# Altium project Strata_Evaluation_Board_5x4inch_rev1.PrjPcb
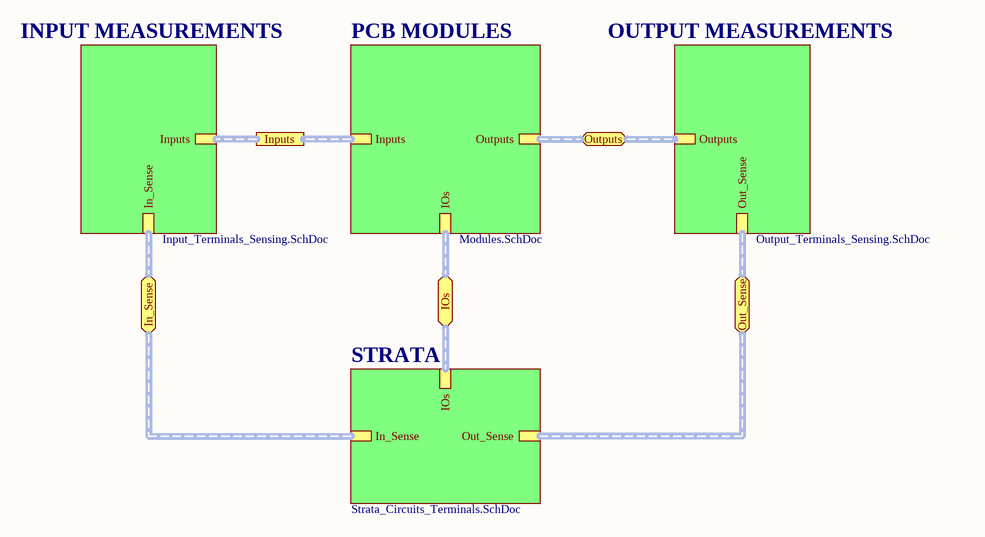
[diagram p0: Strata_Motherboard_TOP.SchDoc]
Project_Author: Miroslav Hukel; Project_CompanyName: ON Semiconductor Slovakia; Project_DateCreated: 01-12-2019; Project_DateModified: DD-MM-YYYY; Project_DocumentNumber: BA0362OA; Project_Revision: O; Project_Title: Strata PCB Module Evaluation Board
5 sheets, 99 parts. Net scope: hierarchical (ports join the sheet entries above them; power ports are global).
Board file: Strata_Evaluation_Board_5x4inch_rev1.PcbDoc
Sheets:
  Strata_Motherboard_TOP.SchDoc
    PCB MODULES = Modules.SchDoc
    OUTPUT MEASUREMENTS = Output_Terminals_Sensing.SchDoc
    STRATA = Strata_Circuits_Terminals.SchDoc
    INPUT MEASUREMENTS = Input_Terminals_Sensing.SchDoc

## Sheet Strata_Motherboard_TOP.SchDoc: =Project_Title
size A4; Author: F. Valero / T. Krecek; CompanyName: ON Semiconductor Slovakia; DocumentNumber: BA0362OA; Revision: 1

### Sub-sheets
INPUT MEASUREMENTS = Input_Terminals_Sensing.SchDoc: Inputs (harness Inputs), In_Sense (harness In_Sense)
OUTPUT MEASUREMENTS = Output_Terminals_Sensing.SchDoc: Outputs (harness Outputs), Out_Sense (harness Out_Sense)
PCB MODULES = Modules.SchDoc: Outputs (harness Outputs), IOs (harness IOs), Inputs (harness Inputs)
STRATA = Strata_Circuits_Terminals.SchDoc: IOs (harness IOs), In_Sense (harness In_Sense), Out_Sense (harness Out_Sense)

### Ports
In_Sense (bidir), Inputs, IOs (bidir), Out_Sense (bidir), Outputs (bidir)

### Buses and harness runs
harness port In_Sense = sheet INPUT MEASUREMENTS/In_Sense = sheet STRATA/In_Sense
harness port Inputs = sheet INPUT MEASUREMENTS/Inputs = sheet PCB MODULES/Inputs
harness port IOs = sheet PCB MODULES/IOs = sheet STRATA/IOs
harness port Out_Sense = sheet OUTPUT MEASUREMENTS/Out_Sense = sheet STRATA/Out_Sense
harness port Outputs = sheet OUTPUT MEASUREMENTS/Outputs = sheet PCB MODULES/Outputs

## Sheet Modules.SchDoc: =Project_ProductNumber + ' ' + Project_Title1 + ' ' + Project_Title2
size A3; Author: F. Valero / T. Krecek; CompanyName: ON Semiconductor Slovakia; DocumentNumber: BA0362OA; Revision: 1; SheetNumber: 1; SheetTotal: 2
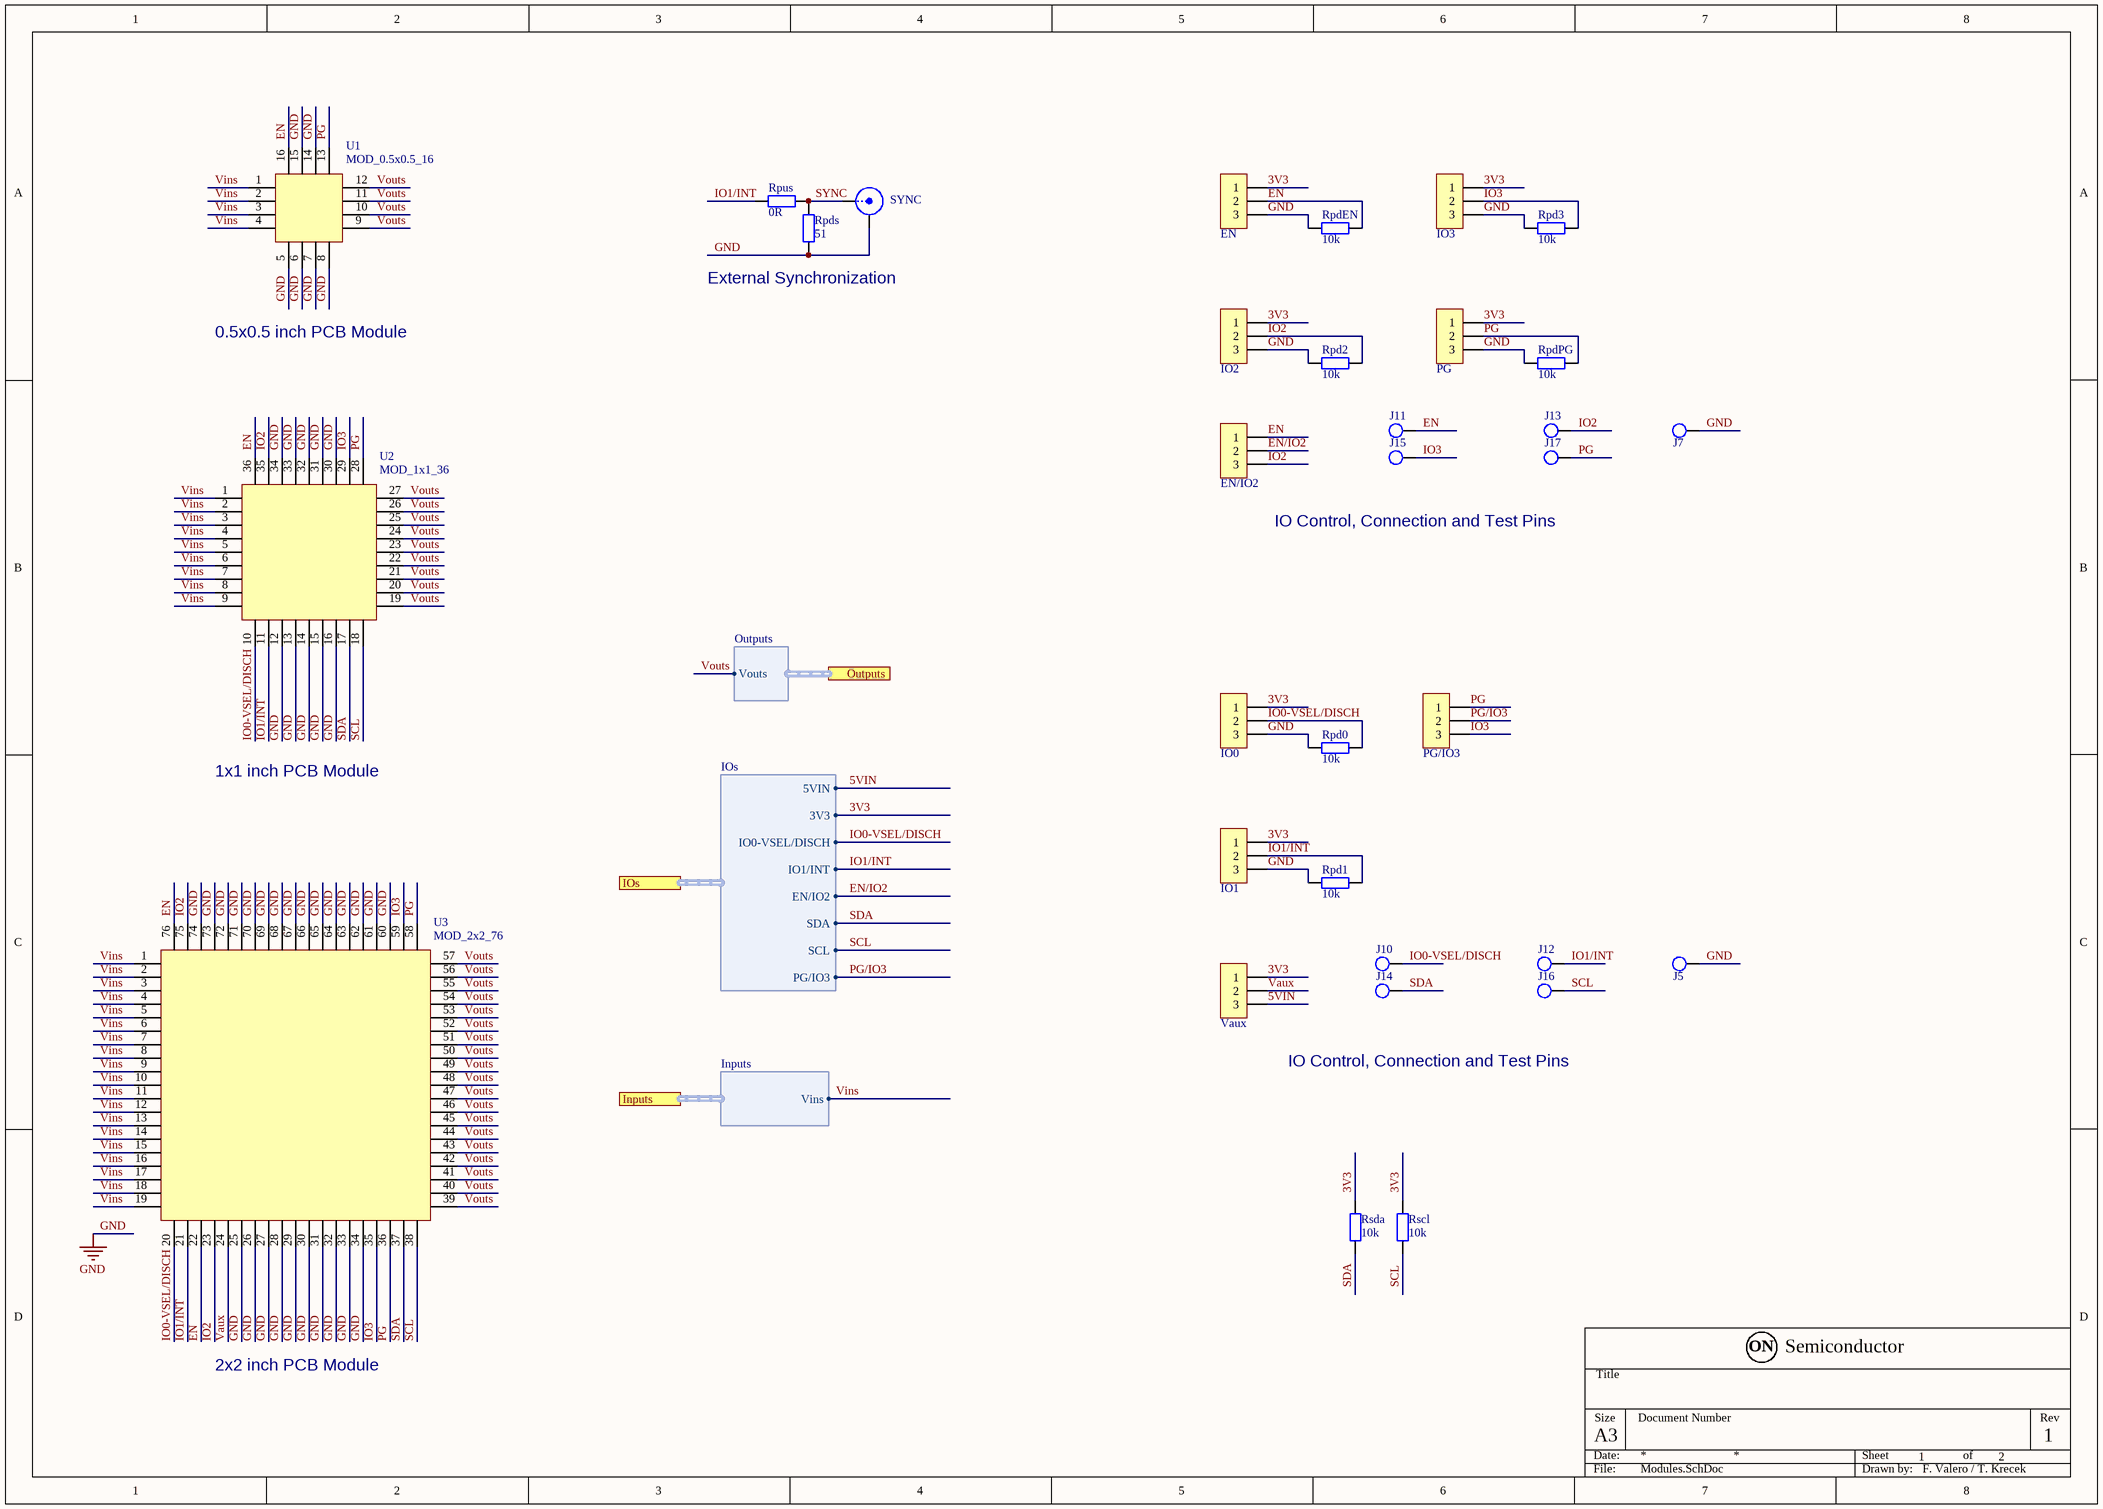
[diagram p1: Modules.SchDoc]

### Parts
EN  22-28-4360  [Header_3]  (value not drawn)
EN/IO2  22-28-4360  [Header_3]  (value not drawn)
IO0  22-28-4360  [Header_3]  (value not drawn)
IO1  22-28-4360  [Header_3]  (value not drawn)
IO2  22-28-4360  [Header_3]  (value not drawn)
IO3  22-28-4360  [Header_3]  (value not drawn)
J5  160-1026-02-01-00  [Terminal Turret]  (value not drawn)
J7  160-1026-02-01-00  [Terminal Turret]  (value not drawn)
J10  5010  [TestPoint_1.6mm]  (value not drawn)
J11  5010  [TestPoint_1.6mm]  (value not drawn)
J12  5010  [TestPoint_1.6mm]  (value not drawn)
J13  5010  [TestPoint_1.6mm]  (value not drawn)
J14  5010  [TestPoint_1.6mm]  (value not drawn)
J15  5010  [TestPoint_1.6mm]  (value not drawn)
J16  5010  [TestPoint_1.6mm]  (value not drawn)
J17  5010  [TestPoint_1.6mm]  (value not drawn)
PG  22-28-4360  [Header_3]  (value not drawn)
PG/IO3  22-28-4360  [Header_3]  (value not drawn)
Rpd0  value 10k  [0603_RES]  (hidden comment: RC0603FR-0710KL)
Rpd1  value 10k  [0603_RES]  (hidden comment: RC0603FR-0710KL)
Rpd2  value 10k  [0603_RES]  (hidden comment: RC0603FR-0710KL)
Rpd3  value 10k  [0603_RES]  (hidden comment: RC0603FR-0710KL)
RpdEN  value 10k  [0603_RES]  (hidden comment: RC0603FR-0710KL)
RpdPG  value 10k  [0603_RES]  (hidden comment: RC0603FR-0710KL)
Rpds  value 51  [0603_RES]  (hidden comment: RC0603FR-0751RL)
Rpus  value 0R  [0603_RES]  (hidden comment: Short)
Rscl  value 10k  [0603_RES]  (hidden comment: RC0603FR-0710KL)
Rsda  value 10k  [0603_RES]  (hidden comment: RC0603FR-0710KL)
SYNC  SMB_STR_TH_50OHM  [SMB_STR_TH]  (value not drawn)
U1  MOD_0.5x0.5_16  [MOD_0.5x0.5_16]
U2  MOD_1x1_36  [MOD_1x1_36]
U3  MOD_2x2_76  [MOD_2x2_76]
Vaux  22-28-4360  [Header_3]  (value not drawn)

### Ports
Inputs (harness Inputs), IOs (harness IOs), Outputs (harness Outputs)

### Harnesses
Outputs: Vouts
Inputs: Vins
IOs: EN/IO2, IO0-VSEL/DISCH, IO1/INT, SDA, PG/IO3, SCL, 3V3, 5VIN

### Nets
GND: EN.3 IO0.3 IO1.3 IO2.3 IO3.3 J5.1 J7.1 PG.3 Rpd0.2 Rpd1.2 Rpd2.2 Rpd3.2 RpdEN.2 RpdPG.2 Rpds.2 SYNC.2 U1.5 U1.6 U1.7 U1.8 U1.14 U1.15 U2.12 U2.13 U2.14 U2.15 U2.16 U2.30 U2.31 U2.32 U2.33 U2.34 U3.25 U3.26 U3.27 U3.28 U3.29 U3.30 U3.31 U3.32 U3.33 U3.34 U3.60 U3.61 U3.62 U3.63 U3.64 U3.65 U3.66 U3.67 U3.68 U3.69 U3.70 U3.71 U3.72 U3.73 U3.74
3V3: EN.1 IO0.1 IO1.1 IO2.1 IO3.1 PG.1 Rscl.1 Rsda.1 Vaux.1 ; port IOs.3V3
5VIN: Vaux.3 ; port IOs.5VIN
EN: EN.2 EN/IO2.1 J11.1 RpdEN.1 U1.16 U2.36 U3.22 U3.76
EN/IO2: EN/IO2.2 ; port IOs.EN/IO2
IO0-VSEL/DISCH: IO0.2 J10.1 Rpd0.1 U2.10 U3.20 ; port IOs.IO0-VSEL/DISCH
IO1/INT: IO1.2 J12.1 Rpd1.1 Rpus.1 U2.11 U3.21 ; port IOs.IO1/INT
IO2: EN/IO2.3 IO2.2 J13.1 Rpd2.1 U2.35 U3.23 U3.75
IO3: IO3.2 J15.1 PG/IO3.3 Rpd3.1 U2.29 U3.35 U3.59
PG: J17.1 PG.2 PG/IO3.1 RpdPG.1 U1.13 U2.28 U3.36 U3.58
PG/IO3: PG/IO3.2 ; port IOs.PG/IO3
SCL: J16.1 Rscl.2 U2.18 U3.38 ; port IOs.SCL
SDA: J14.1 Rsda.2 U2.17 U3.37 ; port IOs.SDA
SYNC: Rpds.1 Rpus.2 SYNC.1
Vaux: U3.24 Vaux.2
Vins: U1.1 U1.2 U1.3 U1.4 U2.1 U2.2 U2.3 U2.4 U2.5 U2.6 U2.7 U2.8 U2.9 U3.1 U3.2 U3.3 U3.4 U3.5 U3.6 U3.7 U3.8 U3.9 U3.10 U3.11 U3.12 U3.13 U3.14 U3.15 U3.16 U3.17 U3.18 U3.19 ; port Inputs.Vins
Vouts: U1.9 U1.10 U1.11 U1.12 U2.19 U2.20 U2.21 U2.22 U2.23 U2.24 U2.25 U2.26 U2.27 U3.39 U3.40 U3.41 U3.42 U3.43 U3.44 U3.45 U3.46 U3.47 U3.48 U3.49 U3.50 U3.51 U3.52 U3.53 U3.54 U3.55 U3.56 U3.57 ; port Outputs.Vouts

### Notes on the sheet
- (near Rpds) External Synchronization
- 0.5x0.5 inch PCB Module
- IO Control, Connection and Test Pins
- 1x1 inch PCB Module
- 2x2 inch PCB Module

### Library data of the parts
EN EN/IO2 IO0-IO3 PG PG/IO3 Vaux = Header3_EB_IO: Board-To-Board Connector; Header; 36;  22-28-4360; Manufacturer: Würth electronics; MPN: 61300311121; Signature Author: Zemanovic; Value/Rating: 3 POS; Value: 3 POS; Substitution Allowed: Yes
J5 J7 = TestPoint_2.37mm: TestPoint; 2.37mm; TH; CAMBION  160-1026-02-01-00  TERMINAL; Signature Author: Nagy; Substitution Allowed: Yes
J10-J17 = TestPoint_1.6mm: TestPoint; 1.6mm; TH; Keystone 5010; Signature Author: Nagy; Substitution Allowed: Yes
Rpd0-Rpd3 RpdEN RpdPG Rscl Rsda = 10k_0603_1%: 10k; 1/10W; 1%; 0603; Yageo; Signature Author: Hukel; Value/Rating: 10k/1/10W; Substitution Allowed: Yes
Rpds = 51_0603_1%: 51; 1/10W; 1%; 0603; Yageo; Signature Author: Hukel; Value/Rating: 51/1/10W; Substitution Allowed: Yes
Rpus = 0R_0603: RES SMD 0 OHM JUMPER 0603; Yageo; MPN: RC2512JK-070RL; Signature Author: Hukel; Rating: 1W; Value/Rating: 0R/1W; Substitution Allowed: Yes
SYNC = SMB_STR_TH_50OHM: SMB JACK STR; 50 OHM; TH; 1-1337482-0; Manufacturer: TE Connectivity; Signature Author: Zemanovic; Substitution Allowed: Yes
U1 = MOD_0.5x0.5_16: PCB Footprint for 0.5 x 0.5 inch PCB Module; Substitution Allowed: No
U2 = MOD_1x1_36: PCB Footprint for 1 x 1 inch PCB Module; Substitution Allowed: No
U3 = MOD_2x2_76: PCB Footprint for 2 x 2 inch PCB Module; Substitution Allowed: No

## Sheet Output_Terminals_Sensing.SchDoc: =Project_Title
size A4; Author: F. Valero / T. Krecek; CompanyName: ON Semiconductor Slovakia; DocumentNumber: BA0362OA; Revision: 1
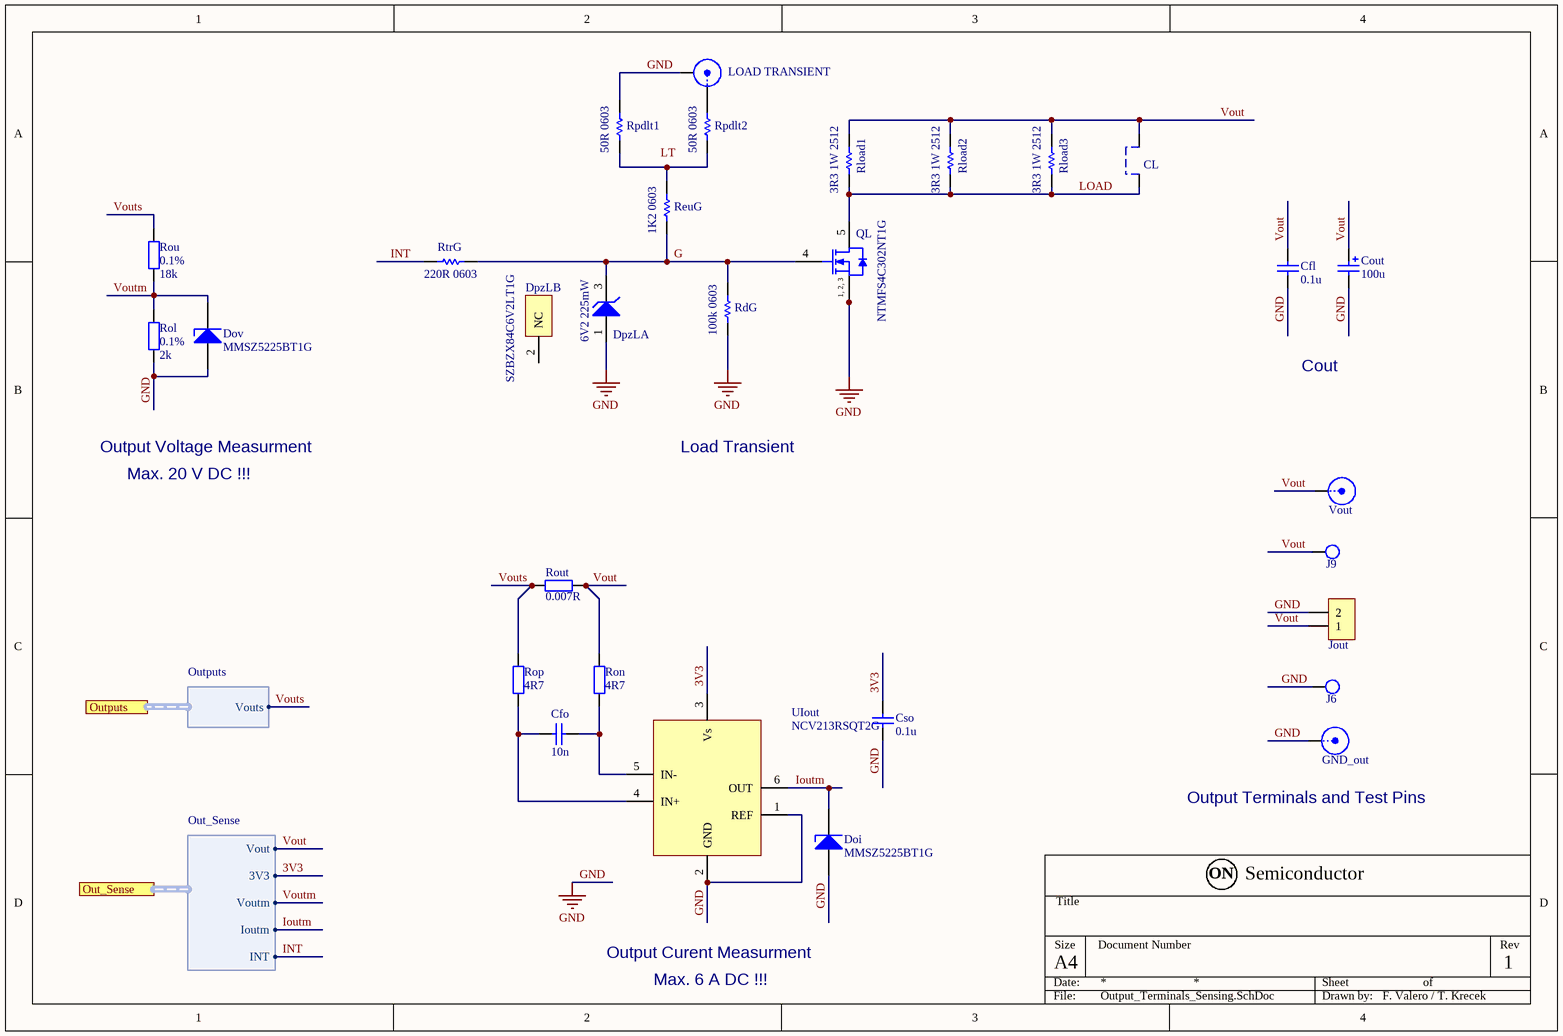
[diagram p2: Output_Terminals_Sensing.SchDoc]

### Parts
Cfl  value 0.1u  [0603_CAP_MAX]  (hidden comment: GCJ188R71H104KA12D)
Cfo  value 10n  [0603_CAP]  (hidden comment: GCJ188R71H103KA01D)
CL  Current Loop for 2.5 sqmm Cu wire  [Current_Loop_2.5sqmm]  (value not drawn)
Cout  value 100u  [Elyt_Radial_10X12.5]  (hidden comment: EEUFR1J101B)
Cso  value 0.1u  [0603_CAP]  (hidden comment: GCJ188R71H104KA12D)
Doi  MMSZ5225BT1G  [SOD-123]
Dov  MMSZ5225BT1G  [SOD-123]
DpzL  6V2 225mW  [ONSC-SOT-23-3-318-08_V]  (parts A,B of 2)
GND_out  571-0100-01  [PCB Jack 4mm - black]  (value not drawn)
J6  160-1026-02-01-00  [Terminal Turret]  (value not drawn)
J9  5010  [TestPoint_1.6mm]  (value not drawn)
Jout  OSTTC022162  [ED120/2DS]  (value not drawn)
LOAD_TRANSIENT  SMB_STR_TH_50OHM  [SMB_STR_TH]  (value not drawn)
QL  NTMFS4C302NT1G  [ONSC-DFN-5-488AA_V]
RdG  100k 0603  [RESC1608X55X25ML10T15]
ReuG  1K2 0603  [RESC1608X55X25LL10T15]
Rload1  3R3 1W 2512  [RESC2512(6432)_N]
Rload2  3R3 1W 2512  [RESC2512(6432)_N]
Rload3  3R3 1W 2512  [RESC2512(6432)_N]
Rol  value 2k  Tolerance: 0.1%  [0603_RES]  (hidden comment: RT0603BRD072KL)
Ron  value 4R7  [0603_RES]  (hidden comment: RC0603FR-074R7L)
Rop  value 4R7  [0603_RES]  (hidden comment: RC0603FR-074R7L)
Rou  value 18k  Tolerance: 0.1%  [0603_RES]  (hidden comment: RT0603BRD0718KL)
Rout  value 0.007R  [2512_RES]  (hidden comment: PE2512FKE7W0R007L)
Rpdlt1  50R 0603  [RESC1609X50X30NL10T20]
Rpdlt2  50R 0603  [RESC1609X50X30NL10T20]
RtrG  220R 0603  [RESC1608X55X25ML10T15]
UIout  value NCV213RSQT2G  [SC-88/SC70-6/SOT-363]  (hidden comment: NCS213R)
Vout  571-0500-01  [PCB Jack 4mm - red]  (value not drawn)

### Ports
Out_Sense (harness Out_Sense), Outputs (harness Outputs)

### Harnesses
Outputs: Vouts
Out_Sense: Voutm, Ioutm, 3V3, Vout, INT

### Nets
GND: Cfl.2 Cout.2 Cso.2 Doi.2(A) Dov.2(A) DpzL.1(A) GND_out.1 J6.1 Jout.2 LOAD_TRANSIENT.2 QL.1(S) QL.2(S) QL.3(S) RdG.2 Rol.2 Rpdlt1.2 UIout.1(REF) UIout.2(GND)
3V3: Cso.1 UIout.3(Vs) ; port Out_Sense.3V3
G: DpzL.3(K) QL.4(G) RdG.1 ReuG.1 RtrG.2
INT: RtrG.1 ; port Out_Sense.INT
Ioutm: Doi.1(K) UIout.6(OUT) ; port Out_Sense.Ioutm
LOAD: CL.1 QL.5(D) Rload1.1 Rload2.1 Rload3.1
Vout: Cfl.1 CL.2 Cout.1 J9.1 Jout.1 Rload1.2 Rload2.2 Rload3.2 Ron.1 Rout.2 Vout.1 ; port Out_Sense.Vout
Voutm: Dov.1(K) Rol.1 Rou.2 ; port Out_Sense.Voutm
Vouts: Rop.1 Rou.1 Rout.1 ; port Outputs.Vouts
NetCfo_1: Cfo.1 Ron.2 UIout.5(IN-)
NetCfo_2: Cfo.2 Rop.2 UIout.4(IN+)
NetLOAD_TRANSIENT_1: LOAD_TRANSIENT.1 Rpdlt2.2
NetReuG_2: ReuG.2 Rpdlt1.1 Rpdlt2.1

Not connected (* = marked no-connect by the designer): DpzL 2(NC)

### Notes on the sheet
- Cout
- Output Voltage Measurment
- Max. 20 V DC !!!
- Load Transient
- (near GND_out) Output Terminals and Test Pins
- Output Curent Measurment
- Max. 6 A DC !!!
- Labels drawn without touching a wire or pin: LT

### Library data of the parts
Cfl Cso = GCJ188R71H104KA12D: 0.1uF; 50V; X7R; 10%; 0603; GRM188R70J474KA01D; Murata; Signature Author: Hukel; Substitution Allowed: Yes; Value/Rating: 0.1u/50V
Cfo = GCJ188R71H103KA01D: 10nF; 50V; X7R; 10%; 0603; GCJ188R71H103KA01D; Murata; Signature Author: Hukel; Substitution Allowed: Yes; Value/Rating: 10n/50V
CL = Current_Loop_2.5sqmm: Current Loop Wire for Osciloscope Current Probe; Signature Author: Hukel; Rating: 1W; Tolerance: Wire Loop; Value/Rating: 0.005/1W; Substitution Allowed: Yes; Value: 0.005
Cout = 100uF_Rad_63V_ELYT: 100uF; 63 V; 20%; EEUFR1J101B; Panasonic; MPN: EEU-FR1J101B; Signature Author: Zemanovic; Rating: 63V; Value/Rating: 100u/63V; Substitution Allowed: Yes
Doi Dov = MMSZ5225BT1G: MMSZ52xxxT1G; 3.0V/0.5W; SOD-123; ON Semiconductor; Signature Author: Nagy; Tolerance: 5%; Substitution Allowed: Yes
DpzL = CMP-1060-00917-1: Zener Voltage Regulator, 225 mW, 3-Pin SOT-23, Pb-Free, Tape and Reel; Manufacturer: On Semiconductor; MPN: SZBZX84C6V2LT1G
GND_out = Banana_Socket_10A_Black: 10A; 4mm; TH; Black; 571-0100-01 ; DELTRON; Signature Author: Nagy; Substitution Allowed: Yes
J6 = TestPoint_2.37mm: as J5 on sheet Modules
J9 = TestPoint_1.6mm: as J10 on sheet Modules
Jout = Screw_Terminal_Large: Large Screw Terminal,  TERM BLK 2P SIDE ENT 5.08MM PCB; Manufacturer: Samtec; Signature Author: Zemanovic; Value/Rating: TSW-102-07-G-S; Value: TSW-102-07-G-S; Substitution Allowed: Yes
LOAD_TRANSIENT = SMB_STR_TH_50OHM: as SYNC on sheet Modules
QL = CMP-1058-00242-1: Single N−Channel Logic Level Power MOSFET, 30 V, 230 A, 1.15 mΩ; Manufacturer: On Semiconductor; Channel Polarity: N Channel; Packing: Tape and Reel; VGS Max (V): 20; VGS(th) Max (V): 2.2; V(BR)DSS Min (V): 30
RdG = CMP-2100-03662-1: Chip Resistor, 100 KOhm, +/- 1%, 0.1 W, -55 to 155 degC, 0603 (1608 Metric), RoHS, Tape and Reel; Manufacturer: Yageo; MPN: RC0603FR-07100KL; Power Rating: 100mW; Voltage Rating: 50V; Temperature Coefficient: 100ppm/degreesC
ReuG = CMP-2000-06952-1: Chip Resistor, 1.2 KOhm, +/- 5%, 0.1 W, -55 to 155 degC, 0603 (1608 Metric), RoHS, Tape and Reel; Manufacturer: Yageo; MPN: RC0603JR-071K2L; Temperature Coefficient: 100PPM/C; Resistance: 1.2kOhms; Power Rating: 100mW; Voltage Rating: 50V
Rload1-Rload3 = CMP-1018-00014-1: 3R3 1W 5% 2512 (6432 Metric)  SMD; Manufacturer: Vishay Dale; MPN: CRCW25123R30JNEG; Value: 3.30 Ohm; Case-EIA: 2512; Case-Metric: 6432
Rol = 1k_0603_0.01%: RES SMD 2K OHM 0.1% 1 / 10W 0603; Manufacturer: Yageo; Signature Author: Valero; Rating: 1/10W; Value/Rating: 2k/1/10W; Substitution Allowed: Yes
Ron Rop = 4.7_0603_1%_1: 4.7; 1/10W; 1%; 0603; Yageo; Signature Author: Hukel; Value/Rating: 4R7/1/10W; Substitution Allowed: Yes
Rou = 5.6k_0603_0.01%: 18 kOhms ± 0.1% 0.1W, 1 / 10W chip resistance 0603 (1608 metric) thin film; Manufacturer: Yageo; Signature Author: Valero; Rating: 1/10W; Value/Rating: 18k/1/10W; Substitution Allowed: Yes
Rout = 0.010R_2512_0.5%: RES SMD 0.007 OHM 2W 2512; Yageo; Signature Author: Hukel; Tolerance: 1%; Value/Rating: 0.007R/2W; Substitution Allowed: Yes
Rpdlt1 Rpdlt2 = CMP-2000-03436-1: Chip Resistor, 50 Ohm, +/- 1%, 0.1 W, -55 to 155 degC, 0603 (1608 Metric), RoHS, Tape and Reel; MPN: CRCW060350R0FKEA; Manufacturer: Vishay Dale
RtrG = CMP-1659-00018-2: General Purpose Chip Resistors, 220 Ohm, +/- 1%, -55 to 155 degC, 0603 (1608 Metric), RoHS, Tape and Reel; MPN: RC0603FR-07220RL
UIout = NCS213R: Current-Shunt Monitors, Voltage Output, Bidirectional Zero-Drift, Low- or High-Side Current Sensing; SO-8; ON Semiconductor; Signature Author: Hukel; Substitution Allowed: No
Vout = Banana_Socket_10A_Red: 10A; 4mm; TH; Red; 571-0500-01 ; DELTRON; Signature Author: Nagy; Substitution Allowed: Yes

## Sheet Strata_Circuits_Terminals.SchDoc: =Project_Title
size A4; Author: F. Valero / T. Krecek; CompanyName: ON Semiconductor Slovakia; DocumentNumber: BA0362OA; Revision: 1
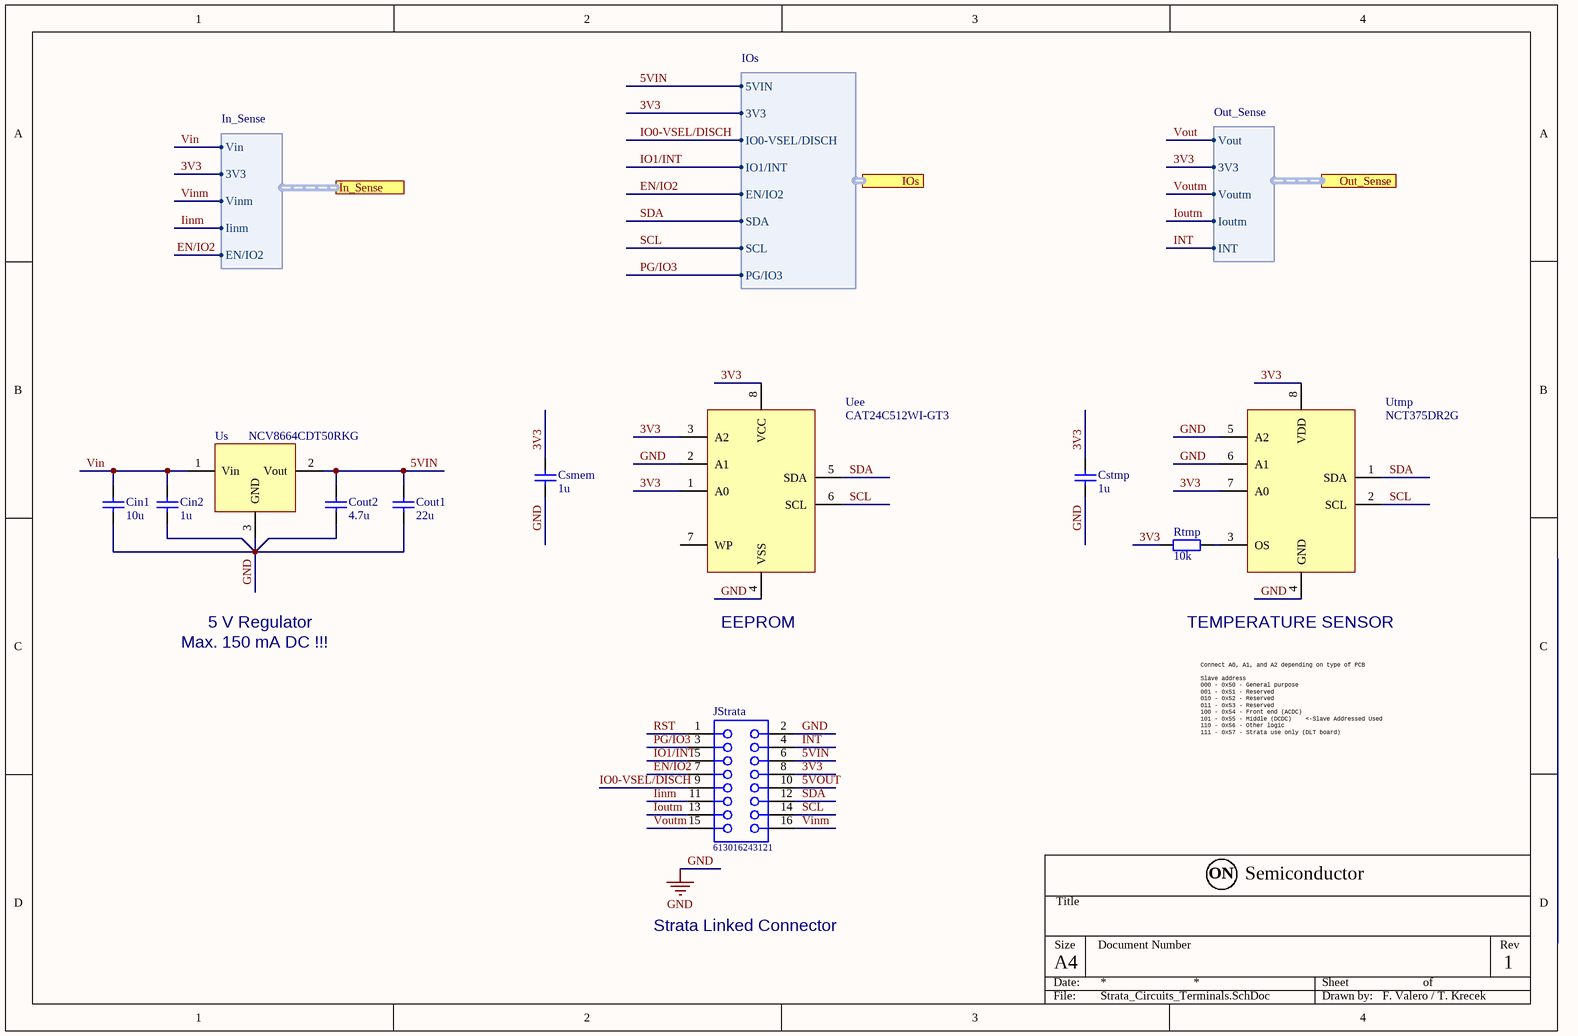
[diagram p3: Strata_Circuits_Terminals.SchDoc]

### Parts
Cin1  value 10u  [1206_CAP]  (hidden comment: GRT31CR71E106KE13)
Cin2  value 1u  [0805_CAP_MAX]  (hidden comment: GCM21BR71H105KA03L)
Cout1  value 22u  [1206_CAP_MAX]  (hidden comment: GCM31CR71A226KE02L)
Cout2  value 4.7u  [0805_CAP_MAX]  (hidden comment: GCM21BR71C475KA73L)
Csmem  value 1u  [0805_CAP_MAX]  (hidden comment: GCM21BR71H105KA03L)
Cstmp  value 1u  [0805_CAP_MAX]  (hidden comment: GCM21BR71H105KA03L)
JStrata  613016243121  [613016243121_Strata]
Rtmp  value 10k  [0603_RES]  (hidden comment: RC0603FR-0710KL)
Uee  value CAT24C512WI-GT3  [SOIC-8]  (hidden comment: CAT24C512)
Us  value NCV8664CDT50RKG  [DPAK-3_L]  (hidden comment: NCV8664CDT50)
Utmp  value NCT375DR2G  [SOIC-8]  (hidden comment: NCT375)

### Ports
In_Sense (harness In_Sense), IOs (harness IOs), Out_Sense (harness Out_Sense)

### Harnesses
In_Sense: Vinm, Iinm, 3V3, Vin, EN/IO2
Out_Sense: Voutm, Ioutm, 3V3, Vout, INT
IOs: EN/IO2, IO0-VSEL/DISCH, IO1/INT, SDA, PG/IO3, SCL, 3V3, 5VIN

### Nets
GND: Cin1.2 Cin2.2 Cout1.2 Cout2.2 Csmem.2 Cstmp.2 JStrata.2 Uee.2(A1) Uee.4(VSS) Us.3(GND) Utmp.4(GND) Utmp.5(A2) Utmp.6(A1)
3V3: Csmem.1 Cstmp.1 JStrata.8 Rtmp.1 Uee.1(A0) Uee.3(A2) Uee.8(VCC) Utmp.7(A0) Utmp.8(VDD) ; port In_Sense.3V3, port Out_Sense.3V3, port IOs.3V3
5VIN: Cout1.1 Cout2.1 JStrata.6 Us.2(Vout) ; port IOs.5VIN
5VOUT: JStrata.10
EN/IO2: JStrata.7 ; port In_Sense.EN/IO2, port IOs.EN/IO2
Iinm: JStrata.11 ; port In_Sense.Iinm
INT: JStrata.4 ; port Out_Sense.INT
IO0-VSEL/DISCH: JStrata.9 ; port IOs.IO0-VSEL/DISCH
IO1/INT: JStrata.5 ; port IOs.IO1/INT
Ioutm: JStrata.13 ; port Out_Sense.Ioutm
PG/IO3: JStrata.3 ; port IOs.PG/IO3
RST: JStrata.1
SCL: JStrata.14 Uee.6(SCL) Utmp.2(SCL) ; port IOs.SCL
SDA: JStrata.12 Uee.5(SDA) Utmp.1(SDA) ; port IOs.SDA
Vin: Cin1.1 Cin2.1 Us.1(Vin) ; port In_Sense.Vin
Vinm: JStrata.16 ; port In_Sense.Vinm
Voutm: JStrata.15 ; port Out_Sense.Voutm
NetRtmp_2: Rtmp.2 Utmp.3(OS)

Not connected (* = marked no-connect by the designer): Uee 7(WP)

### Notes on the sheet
- Max. 150 mA DC !!!
- 5 V Regulator
- (near Uee) EEPROM
- (near Utmp) TEMPERATURE SENSOR
- Connect A0, A1, and A2 depending on type of PCB
  Slave address
  000 - 0x50 - General purpose
  001 - 0x51 - Reserved
  010 - 0x52 - Reserved
  011 - 0x53 - Reserved
  100 - 0x54 - Front end (ACDC)
  101 - 0x55 - Middle (DCDC)    <-Slave Addressed Used
  110 - 0x56 - Other logic
  111 - 0x57 - Strata use only (DLT board)
- Strata Linked Connector

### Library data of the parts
Cin1 = GRT31CR71E106KE13: 10uF; 25V; X7R; 10%; 1206; GRT31CR71E106KE13; Murata; MPN: GRM32EE70G107ME19L; Signature Author: Hukel; Substitution Allowed: Yes; Value/Rating: 10u/25V
Cin2 Csmem Cstmp = GCM21BR71H105KA03L: 1uF; 50V; X7R; 10%; 0805; GCM21BR71H105KA03L; Murata; Signature Author: Hukel; Substitution Allowed: Yes; Value/Rating: 1u/50V
Cout1 = GCM31CR71A226KE02L: 22uF; 10V; X7R; 10%; 1206; GCM31CR71A226KE02L; Murata; Signature Author: Hukel; Substitution Allowed: Yes; Value/Rating: 22u/10V
Cout2 = GCM21BR71C475KA73L: 4.7uF; 10V; X7R; 10%; 0805; GCM21BR71C475KA73L; Murata; Signature Author: Hukel; Substitution Allowed: Yes; Value/Rating: 4.7u/10V
JStrata = 613016243121_STRATA: THT Angled Socket Header WR-PHD, Pitch 2.54 mm, Dual Row, 16 pins; Manufacturer: WUERTH ELECTRONIC; Pin Number: 16; Pitch: 2.54 mm; Gender: Female; Rated Current: 3 A; Working Voltage: 250 VAC; Withstanding Voltage: 500 VAC; Contact Resistance: 20 mOhm; Substitution Allowed: Yes; Signature Author: Hukel
Rtmp = 10k_0603_1%: as Rpd0 on sheet Modules
Uee = CAT24C512: EEPROM Serial 512-Kb I2C; SO-8; ON Semiconductor; MPN: CAT24C512WI GT3; Signature Author: Hukel; Substitution Allowed: No
Us = NCV8664C: NCV8664C; 5V/150mA, 2.0% Very Low Iq, Low Dropout Linear Regulator; DPAK-3; ON Semiconductor; Signature Author: Hukel; Substitution Allowed: No
Utmp = NCT375: Industry Standard Digital Temperature Sensor with / 2‐wire Interface; SO-8; ON Semiconductor; Signature Author: Hukel; Substitution Allowed: No

## Sheet Input_Terminals_Sensing.SchDoc: =Project_Title
size A4; Author: F. Valero / T. Krecek; CompanyName: ON Semiconductor Slovakia; DocumentNumber: BA0362OA; Revision: O
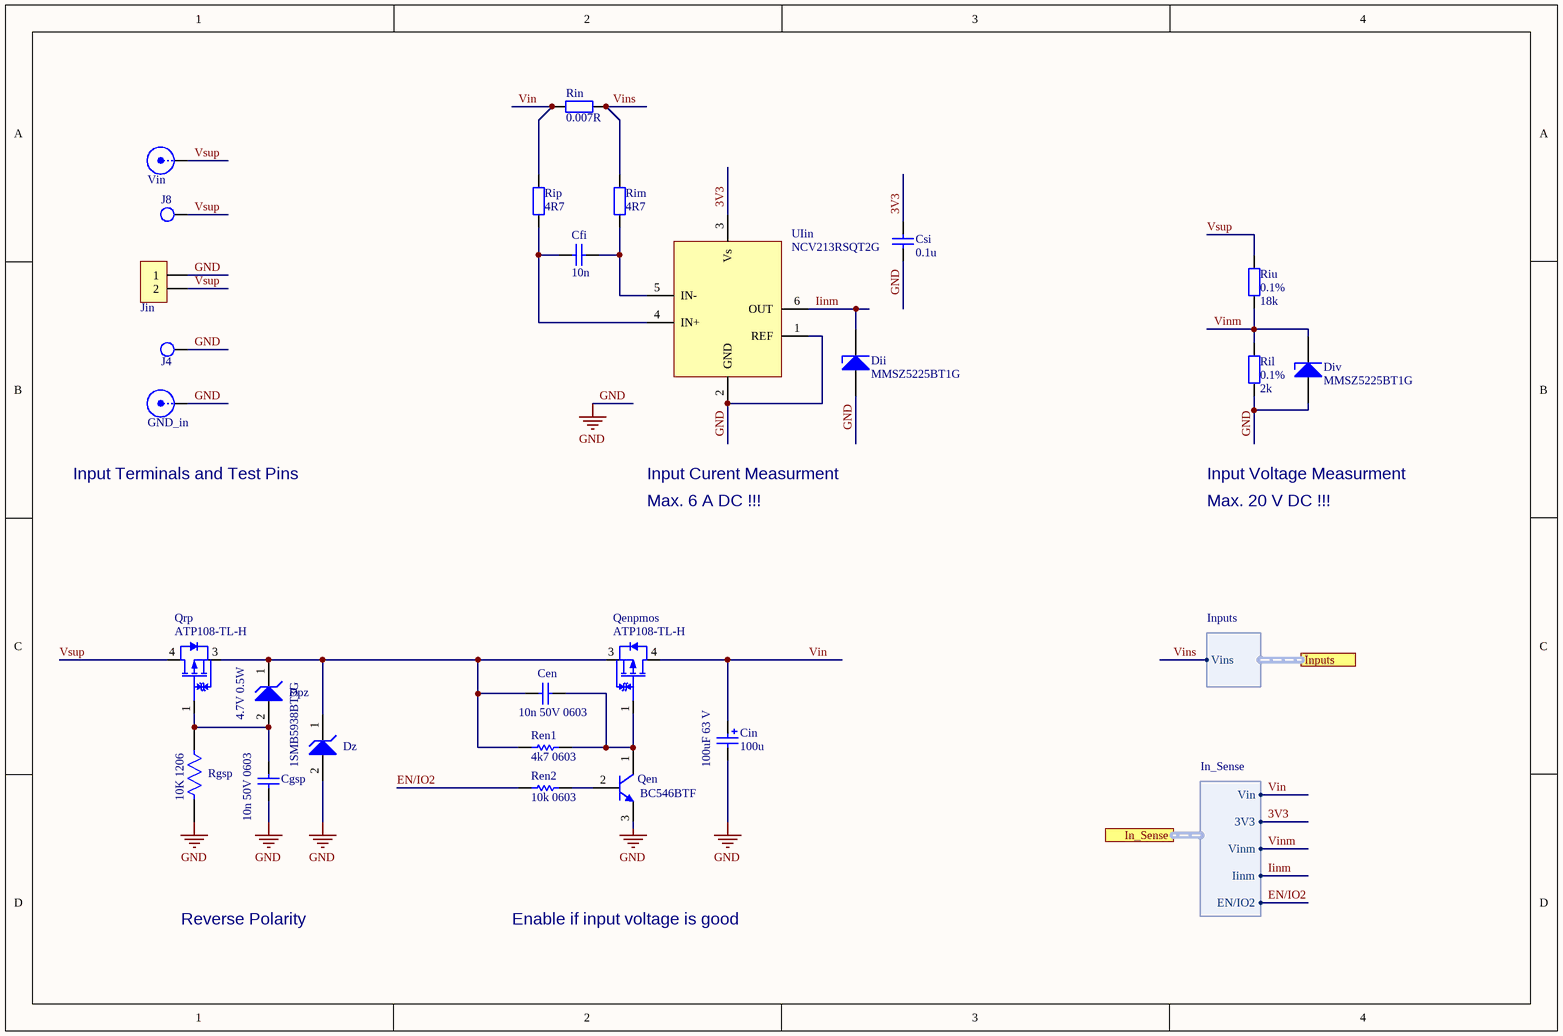
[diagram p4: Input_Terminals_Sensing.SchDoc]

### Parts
Cen  10n 50V 0603  [CAPC1608X90X40ML10T20]
Cfi  value 10n  [0603_CAP]  (hidden comment: GCJ188R71H103KA01D)
Cgsp  10n 50V 0603  [CAPC1608X90X40ML10T20]
Cin  100uF 63 V  value 100u  [Elyt_Radial_10X12.5]
Csi  value 0.1u  [0603_CAP]  (hidden comment: GCJ188R71H104KA12D)
Dii  MMSZ5225BT1G  [SOD-123]
Div  MMSZ5225BT1G  [SOD-123]
Dpz  4.7V 0.5W  [ONSC-SOD-123-2-425-04_V]
Dz  1SMB5938BT3G  [ONSC-SMB-2-403A-03_H_V]
GND_in  571-0100-01  [PCB Jack 4mm - black]  (value not drawn)
J4  160-1026-02-01-00  [Terminal Turret]  (value not drawn)
J8  5010  [TestPoint_1.6mm]  (value not drawn)
Jin  OSTTC022162  [ED120/2DS]  (value not drawn)
Qen  BC546BTF  [ONSC-TO-92-3-29-11]
Qenpmos  ATP108-TL-H  [ONSC-ATPAK-3-369AM_V]
Qrp  ATP108-TL-H  [ONSC-ATPAK-3-369AM_V]
Ren1  4k7 0603  [RESC1608X55X25LL10T15]
Ren2  10k 0603  [RESC1608X55X25ML10T15]
Rgsp  10K 1206  [FP-RC3216-IPC_B]
Ril  value 2k  Tolerance: 0.1%  [0603_RES]  (hidden comment: RT0603BRD072KL)
Rim  value 4R7  [0603_RES]  (hidden comment: RC0603FR-074R7L)
Rin  value 0.007R  [2512_RES]  (hidden comment: PE2512FKE7W0R007L)
Rip  value 4R7  [0603_RES]  (hidden comment: RC0603FR-074R7L)
Riu  value 18k  Tolerance: 0.1%  [0603_RES]  (hidden comment: RT0603BRD0718KL)
UIin  value NCV213RSQT2G  [SC-88/SC70-6/SOT-363]  (hidden comment: NCS213R)
Vin  571-0500-01  [PCB Jack 4mm - red]  (value not drawn)

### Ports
In_Sense (harness In_Sense), Inputs (harness Inputs)

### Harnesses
Inputs: Vins
In_Sense: Vinm, Iinm, 3V3, Vin, EN/IO2

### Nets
GND: Cgsp.1 Cin.2 Csi.2 Dii.2(A) Div.2(A) Dz.2(A) GND_in.1 J4.1 Jin.1 Qen.3(E) Rgsp.2 Ril.2 UIin.1(REF) UIin.2(GND)
3V3: Csi.1 UIin.3(Vs) ; port In_Sense.3V3
EN/IO2: Ren2.1 ; port In_Sense.EN/IO2
Iinm: Dii.1(K) UIin.6(OUT) ; port In_Sense.Iinm
Vin: Cin.1 Qenpmos.4(D) Rin.1 Rip.1 ; port In_Sense.Vin
Vinm: Div.1(K) Ril.1 Riu.2 ; port In_Sense.Vinm
Vins: Rim.1 Rin.2 ; port Inputs.Vins
Vsup: J8.1 Jin.2 Qrp.4(D) Riu.1 Vin.1
NetCen_1: Cen.1 Qen.1(C) Qenpmos.1(G) Ren1.2
NetCen_2: Cen.2 Dpz.1(K) Dz.1(K) Qenpmos.3(S) Qrp.3(S) Ren1.1
NetCfi_1: Cfi.1 Rim.2 UIin.5(IN-)
NetCfi_2: Cfi.2 Rip.2 UIin.4(IN+)
NetCgsp_2: Cgsp.2 Dpz.2(A) Qrp.1(G) Rgsp.1
NetQen_2: Qen.2(B) Ren2.2

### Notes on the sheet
- Input Terminals and Test Pins
- Input Curent Measurment
- Max. 6 A DC !!!
- Input Voltage Measurment
- Max. 20 V DC !!!
- Reverse Polarity
- Enable if input voltage is good

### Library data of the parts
Cen Cgsp = CMP-2100-03600-1: Chip Capacitor, 10 nF, +/- 10%, 50 V, -55 to 125 degC, 0603 (1608 Metric), RoHS, Tape and Reel; Manufacturer: Yageo; MPN: CC0603KRX7R9BB103; Insulation Resistance: 100GR; Dielectric: X7R; Capacitance: 10nF
Cfi = GCJ188R71H103KA01D: as Cfo on sheet Output_Terminals_Sensing
Cin = 100uF_Rad_63V_ELYT: 100uF; 63 V; 20%; EEUFR1J101B; Panasonic; Signature Author: Zemanovic; Rating: 63V; Value/Rating: 100u/63V; Substitution Allowed: Yes
Csi = GCJ188R71H104KA12D: as Cfl on sheet Output_Terminals_Sensing
Dii Div = MMSZ5225BT1G: as Doi on sheet Output_Terminals_Sensing
Dpz = CMP-1060-00571-1: Zener Voltage Regulator, 500 mW, 2-Pin SOD-123, Pb-Free, Tape and Reel; Manufacturer: On Semiconductor; MPN: MMSZ5230BT1G; VZ Typ (V): 4.7; P Max (W): 0.5
Dz = CMP-1060-00144-1: 36V, 3 W Zener Voltage Regulator, 2-Pin SMB, Pb-Free, Tape and Reel; Manufacturer: On Semiconductor; VZ Typ (V): 36
GND_in = Banana_Socket_10A_Black: as GND_out on sheet Output_Terminals_Sensing
J4 = TestPoint_2.37mm: as J5 on sheet Modules
J8 = TestPoint_1.6mm: as J10 on sheet Modules
Jin = Screw_Terminal_Large: as Jout on sheet Output_Terminals_Sensing
Qen = CMP-1048-01466-1: Amplifier Transistor, NPN Silicon, 3-Pin TO-92, Bulk Box; PartNumber: BC546B; Manufacturer: On Semiconductor; IC Continuous (A): 0.1; Note1: 0; fT Min (MHz): 150
Qenpmos Qrp = CMP-1058-00013-1: P-Channel Power MOSFET, -40 V, -70 A, 10.4 mOhm, Single, 3-Pin ATPAK, Pb-Free, Tape and Reel; Manufacturer: On Semiconductor; Coss Typ (pF): 560; Ciss Typ (pF): 3850; VGS(th) Max (V): 2.6; PD Max (W): 60; ID Max (A): 70; Crss Typ (pF): 390; Channel Polarity: P Channel; V(BR)DSS Min (V): 40; VGS Max (V): 20
Ren1 = CMP-2000-06942-1: Chip Resistor, 4.7 KOhm, +/- 1%, 0.1 W, -55 to 155 degC, 0603 (1608 Metric), RoHS, Tape and Reel; Manufacturer: Yageo; MPN: RC0603FR-074K7L; Power Rating: 100mW; Temperature Coefficient: 100PPM/C; Resistance: 4.7kOhms; Voltage Rating: 50V
Ren2 = CMP-2100-03664-1: Chip Resistor, 10 KOhm, +/- 1%, 01 W, -55 to 155 degC, 0603 (1608 Metric), RoHS, Tape and Reel; Manufacturer: Yageo; MPN: RC0603FR-0710KL; Temperature Coefficient: 100ppm/degreesC; Resistance: 10KOhm; Voltage Rating: 75V; Power Rating: 100mW; Voltage Rating (DC): 50V
Rgsp = CMP-13261-000768-1: RES SMD 10K OHM 1% 1/4W 1206; MPN: RC3216F103CS; Manufacturer: Samsung Electro-Mechanics; Resistance: 10kR; Temperature Coefficient: 100ppm/°C; Max Power Dissipation: 250mW; Voltage Rating (DC): 200V
Ril = 1k_0603_0.01%: as Rol on sheet Output_Terminals_Sensing
Rim Rip = 4.7_0603_1%_1: as Ron on sheet Output_Terminals_Sensing
Rin = 0.010R_2512_0.5%: as Rout on sheet Output_Terminals_Sensing
Riu = 5.6k_0603_0.01%: as Rou on sheet Output_Terminals_Sensing
UIin = NCS213R: as UIout on sheet Output_Terminals_Sensing
Vin = Banana_Socket_10A_Red: as Vout on sheet Output_Terminals_Sensing

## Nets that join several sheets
GND: Modules (57 pins), Output_Terminals_Sensing (18 pins), Strata_Circuits_Terminals (13 pins), Input_Terminals_Sensing (14 pins)
3V3: Modules (9 pins), Output_Terminals_Sensing (Cso.1 UIout.3), Strata_Circuits_Terminals (9 pins), Input_Terminals_Sensing (Csi.1 UIin.3)
5VIN: Modules (Vaux.3), Strata_Circuits_Terminals (Cout1.1 Cout2.1 JStrata.6 Us.2)
EN/IO2: Modules (EN/IO2.2), Strata_Circuits_Terminals (JStrata.7), Input_Terminals_Sensing (Ren2.1)
Iinm: Strata_Circuits_Terminals (JStrata.11), Input_Terminals_Sensing (Dii.1 UIin.6)
INT: Output_Terminals_Sensing (RtrG.1), Strata_Circuits_Terminals (JStrata.4)
IO0-VSEL/DISCH: Modules (5 pins), Strata_Circuits_Terminals (JStrata.9)
IO1/INT: Modules (6 pins), Strata_Circuits_Terminals (JStrata.5)
Ioutm: Output_Terminals_Sensing (Doi.1 UIout.6), Strata_Circuits_Terminals (JStrata.13)
PG/IO3: Modules (PG/IO3.2), Strata_Circuits_Terminals (JStrata.3)
SCL: Modules (J16.1 Rscl.2 U2.18 U3.38), Strata_Circuits_Terminals (JStrata.14 Uee.6 Utmp.2)
SDA: Modules (J14.1 Rsda.2 U2.17 U3.37), Strata_Circuits_Terminals (JStrata.12 Uee.5 Utmp.1)
Vin: Strata_Circuits_Terminals (Cin1.1 Cin2.1 Us.1), Input_Terminals_Sensing (Cin.1 Qenpmos.4 Rin.1 Rip.1)
Vinm: Strata_Circuits_Terminals (JStrata.16), Input_Terminals_Sensing (Div.1 Ril.1 Riu.2)
Vins: Modules (32 pins), Input_Terminals_Sensing (Rim.1 Rin.2)
Voutm: Output_Terminals_Sensing (Dov.1 Rol.1 Rou.2), Strata_Circuits_Terminals (JStrata.15)
Vouts: Modules (32 pins), Output_Terminals_Sensing (Rop.1 Rou.1 Rout.1)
